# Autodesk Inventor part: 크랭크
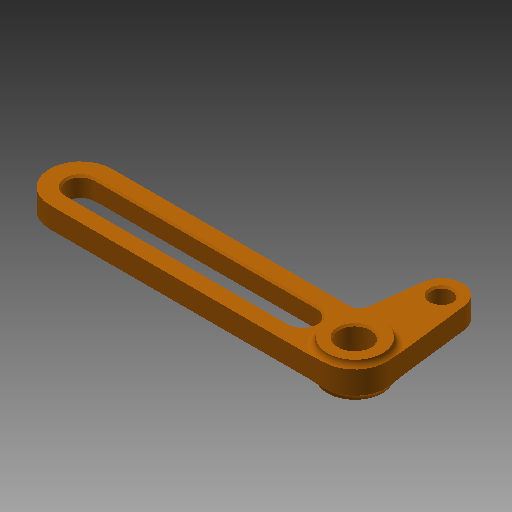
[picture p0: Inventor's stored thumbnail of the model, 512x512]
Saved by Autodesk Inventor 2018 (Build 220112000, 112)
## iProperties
Created: 2019-09
Part Number: 크랭크
Material: 알루미늄 6061
Document SubType Name: Modeling
Designer: mduedu
Density: 2.71 g/cm^3
Appearance: 주황색
Mass: 23.016 g
Surface Area: 54.7149 cm^2
Volume: 8.493 cm^3
Author: mduedu
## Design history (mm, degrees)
sketch "스케치1"
  geometry: L1 (0, 0)-(79, 0); L2 (0, 9)-(79, 9); L3 (10.637, -9)-(79, -9); L4 (0, 0)-(0, -25); L5 (-8.935, -1.08)-(-5.957, -25.72); L6 (7.659, -11.64)-(5.957, -25.72); L7 (79, -4)-(15, -4); L8 (15, 4)-(79, 4); C1 r 3 at (0, -25); A1 r 9 centre (0, 0) between (0, 9) and (-8.935, -1.08); A2 r 9 centre (79, 0) between (79, -9) and (79, 9); A3 r 6 centre (0, -25) between (-5.957, -25.72) and (5.957, -25.72); A4 r 3 centre (10.637, -12) between (10.637, -9) and (7.659, -11.64); A5 r 4 centre (79, 0) between (79, -4) and (79, 4); A6 r 4 centre (15, 0) between (15, -4) and (15, 4); 1 further point
  constraints: 16 end point, 13 point on circle, 12 tangent, 7 centre point, 5 coincident, 3 horizontal, 2 point on line, 1 equal radius, 1 perpendicular, 1 other
  dimensions: "d0" = 79 distance of L1.start L1.end; "d2" = 25 distance of L1.start L4.end; "d3" = 3 radius of A4; "d4" = 9 radius of A1; "d5" = 6 radius of A3; "d6" = 8 diameter of A5; "d7" = 64 distance of A6.centre L1.end; "d8" = 6 diameter of C1
extrude "돌출1" new body sketch "스케치1" stored distance "d9" = 6; taper "d10" = 0 deg
sketch "스케치2"
  geometry: C1 r 8 at (0, 0); 1 further point
  constraints: 1 centre point, 1 coincident
  dimensions: "d11" = 16 diameter of C1
extrude "돌출2" join sketch "스케치2" stored distance "d12" = 10; taper "d13" = 0 deg
sketch "스케치3"
  geometry: C1 r 4.5 at (0, 0); 1 further point
  constraints: 1 centre point, 1 coincident
  dimensions: "d14" = 9 diameter of C1
extrude "돌출3" cut sketch "스케치3" extent not by distance; stored distance "d15" = 10; taper "d16" = 0 deg
fillet "모깎기1" dims "d17" = 2
chamfer "모따기1" distance "d18" = 0.5; stored, may be unused: second distance "d19" = 2, angle "d20" = 45 deg
node "솔리드1"
